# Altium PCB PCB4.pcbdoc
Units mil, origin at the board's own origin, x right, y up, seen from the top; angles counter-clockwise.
Board outline 4551.38 x 1867.22 mil, 2 copper layers (Top Layer, Bottom Layer), stack 2.757 mil thick; 11 components, 15 nets, 42 pads, 2 vias.
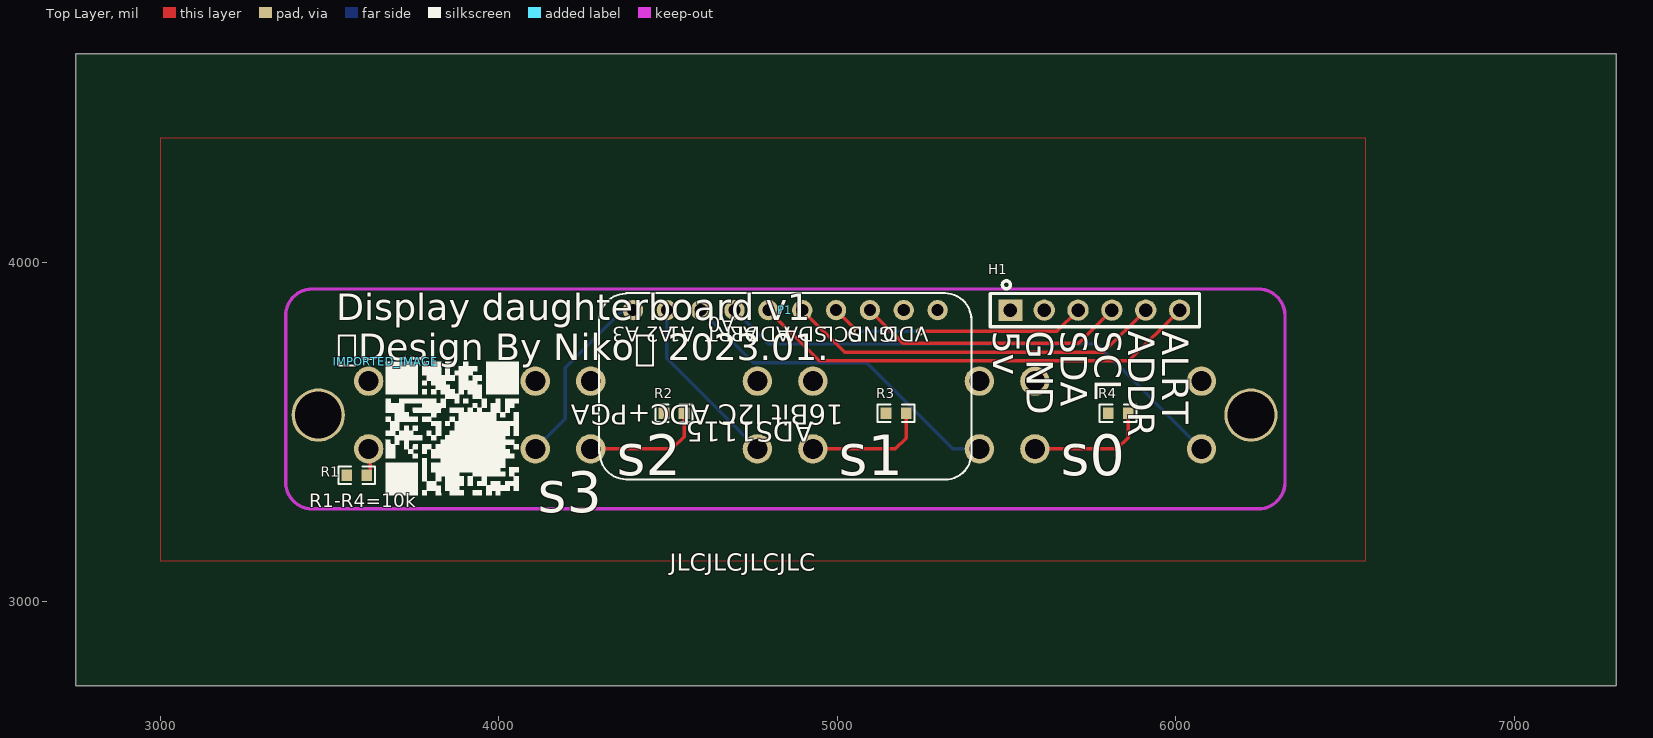
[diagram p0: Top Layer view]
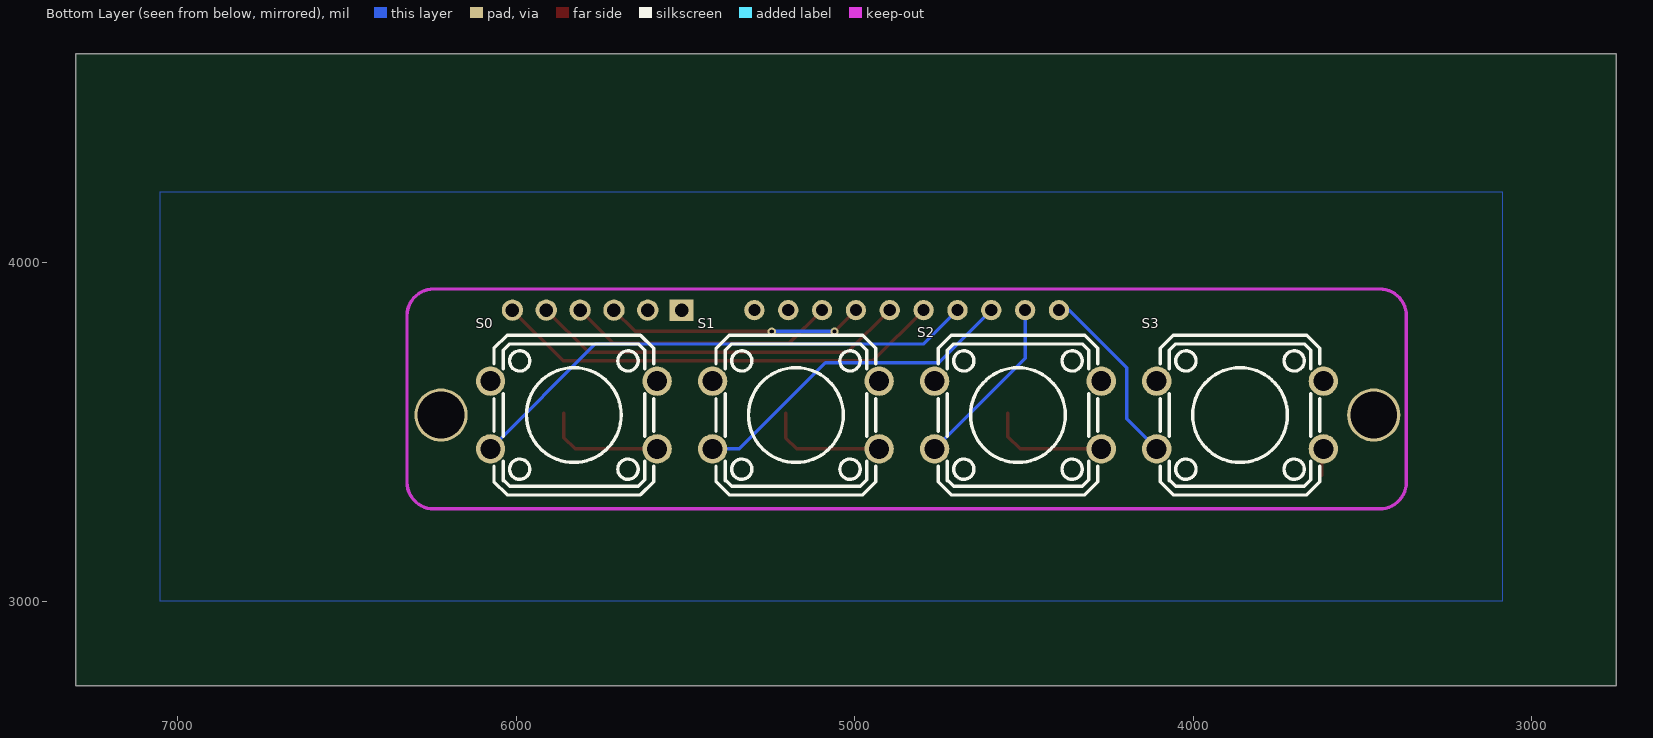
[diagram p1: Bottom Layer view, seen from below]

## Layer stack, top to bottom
Top Layer: signal copper 1.379
Bottom Layer: signal copper 1.378

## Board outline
7301.38,2750 2750,2750 2750,4617.22 7301.38,4617.22

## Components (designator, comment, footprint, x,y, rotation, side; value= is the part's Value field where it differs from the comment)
H1 "HDR-F_2.54_1x6P" HDR-TH_6P-P2.54-V-F 5761.38,3860 r0 top
IMPORTED_IMAGE "IMPORTED_IMAGE" IMPORTED_IMAGE 3665,3707.22 r0 top
P1 "ADS1115" "ADS1115 BREAKOUT BOARD" 5406.38,3910 r180 top
R1 "Res_0603" R0603 3580,3372.22 r0 top
R2 "Res_0603" R0603 4517.56,3555 r0 top
R3 "Res_0603" R0603 5173.74,3555 r0 top
R4 "Res_0603" R0603 5829.92,3555 r0 top
S0 "TS-1003-07026" KEY-TH_4P-L12.0-W12.0-P5.00-LS12.5 5829.92,3550 r180 bottom
S1 "TS-1003-07026" KEY-TH_4P-L12.0-W12.0-P5.00-LS12.5 5173.74,3550 r180 bottom
S2 "TS-1003-07026" KEY-TH_4P-L12.0-W12.0-P5.00-LS12.5 4517.56,3550 r180 bottom
S3 "TS-1003-07026" KEY-TH_4P-L12.0-W12.0-P5.00-LS12.5 3861.38,3550 r180 bottom

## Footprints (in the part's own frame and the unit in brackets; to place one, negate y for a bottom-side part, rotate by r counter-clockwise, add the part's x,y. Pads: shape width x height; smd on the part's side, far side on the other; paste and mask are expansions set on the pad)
"ADS1115 BREAKOUT BOARD" [mil]
  round 60 hole 36: 1(110,50) 2(210,50) 3(310,50) 4(410,50) 5(510,50) 6(610,50) 7(710,50) 8(810,50) 9(910,50) 10(1010,50)
  silkscreen extent 10,0 1110,551
HDR-TH_6P-P2.54-V-F [mm]
  rect 1.8x1.6 hole 1.02: 1(-6.35,0)
  round 1.6 hole 1.02: 2(-3.81,0) 3(-1.27,0) 4(1.27,0) 5(3.81,0) 6(6.35,0)
  silkscreen extent -7.85,-1.25 7.85,2.2
IMPORTED_IMAGE [mil]
  silkscreen extent 0,-394 394,0
KEY-TH_4P-L12.0-W12.0-P5.00-LS12.5 [mm]
  round 2.2 hole 1.5: 1(-6.251,2.54) 2(6.251,2.54) 3(-6.251,-2.54) 4(6.251,-2.54)
  silkscreen extent -5.99,-6 5.99,6
R0603 [mil]
  rect 31.75x34.02 smd: 1(-29.66,0) 2(29.66,0)
  silkscreen extent -55,-26 55,26

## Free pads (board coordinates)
  round 157.48 hole 137.8: 1(3466.38,3550) 1(6222.28,3550)

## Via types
v1: diameter 24.02, hole 12.01, Top Layer to Bottom Layer, 2 vias

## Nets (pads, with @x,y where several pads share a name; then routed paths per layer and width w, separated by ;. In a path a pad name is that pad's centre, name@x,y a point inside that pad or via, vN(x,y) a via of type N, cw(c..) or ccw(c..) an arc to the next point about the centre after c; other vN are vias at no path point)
5V: H1.1 P1.1 S0.2 S1.2 S2.2 S3.2
$1N670: R1.2 S3.4 | length 80.1
  Top Layer w10: S3.4 3620,3445.28 R1.2@3620,3371.88
$1N740: R2.2 S2.4 | length 359.8
  Top Layer w10: S2.4 4511.38,3450 4547.22,3485.84 R2.2
$1N810: R3.2 S1.4 | length 362
  Top Layer w10: S1.4 5171.38,3450 5203.4,3482.02 R3.2
$1N880: R4.2 S0.4 | length 361.3
  Top Layer w10: S0.4 5826.38,3450 5859.58,3483.2 R4.2
$1N1444: P1.7 S0.3 | length 1549.5
  Bottom Layer w10: P1.7 4796.38,3760 5766.02,3760 S0.3
$1N1452: P1.8 S1.3 | length 993.3
  Bottom Layer w10: P1.8 4751.38,3705 5086.38,3705 5341.38,3450 S1.3
$1N1460: P1.9 S2.3 | length 520.7
  Bottom Layer w10: P1.9 4496.38,3717.28 S2.3
$1N1468: P1.10 S3.3 | length 547.2
  Bottom Layer w10: S3.3 4196.38,3538.9 4196.38,3690 4366.38,3860 P1.10
ADDR: H1.5 P1.5 | length 1118.6
  Top Layer w10: P1.5 5021.38,3735 5786.38,3735 H1.5
ALRT: H1.6 P1.6 | length 1339.3
  Top Layer w10: P1.6 4946.38,3710 5861.38,3710 H1.6
GND: H1.2 P1.2 R1.1 R2.1 R3.1 R4.1
SCL: H1.4 P1.3 | length 776.1
  Top Layer w10: P1.3 5194.16,3762.22 5713.6,3762.22 H1.4@5797.33,3845.95
SDA: H1.3 P1.4 | length 767
  Top Layer w10: P1.4 5059.16,3797.22 v1(5060,3797.22) ; v1(5245,3797.22) 5648.6,3797.22 H1.3
  Bottom Layer w10: v1(5060,3797.22) v1(5245,3797.22)
"": pad.1 S0.1 S1.1 S2.1 S3.1

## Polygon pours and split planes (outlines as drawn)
GND on Top Layer (solid, pour order 0): 3000,3120 6561.38,3120 6561.38,4367.22 3000,4367.22
5V on Bottom Layer (solid, pour order 1): 3086.38,3000 7051.38,3000 7051.38,4210 3086.38,4210

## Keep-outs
Keep-Out Layer:
  lines w10 net "": 3370,3351.34 ccw(c3448.74,3351.34) 3448.74,3272.6 6244.02,3272.6 ccw(c6244.02,3351.34) 6322.76,3351.34 6322.76,3843.86 ccw(c6244.02,3843.86) 6244.02,3922.6 3448.74,3922.6 ccw(c3448.74,3843.86) 3370,3843.86 3370,3351.34

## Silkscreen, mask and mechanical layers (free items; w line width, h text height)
Top Silkscreen Layer:
  text "5v" at 5460.08,3799.63 h78.74 r270
  text "GND" at 5560.08,3799.63 h78.74 r270
  text "SDA" at 5660.08,3799.63 h78.74 r270
  text "SCL" at 5760.08,3799.63 h78.74 r270
  text "ADDR" at 5860.08,3799.63 h78.74 r270
  text "ALRT" at 5960.08,3799.63 h78.74 r270
  text "Display daughterboard v1 /  Design By NikoⒸ 2023.01." at 3520,3712.22 h78.74
  text "s2" at 4347.56,3372 h120
  text "s1" at 5003.74,3372 h120
  text "s0" at 5659.92,3372 h120
  text "R1-R4=10k" at 3440,3277.22 h39.37
  text "s3" at 4115,3262.22 h120
  text "JLCJLCJLCJLC" at 4505.44,3089.7 h51.1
